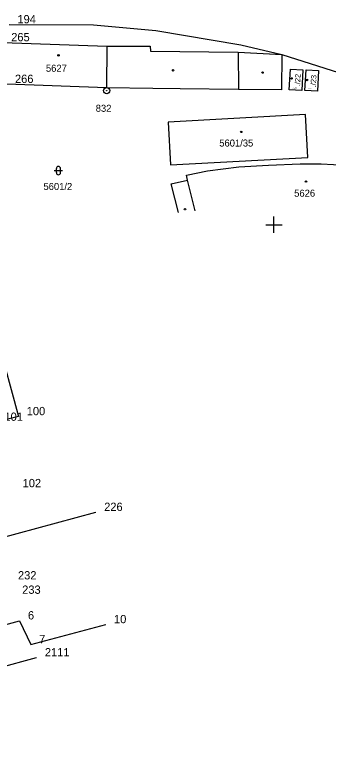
# Model space of a CAD drawing. Extents: x -822293 to -820259, y -1071573 to -1068794.
# Drawn here: x -821162.5 to -821086.9, y -1070329.7 to -1070149.3 of the extents above; entities that cross this region are included whole.
import ezdxf

# ---------------------------------------------------------------- set-up
doc = ezdxf.new("R2010")
doc.units = 0
for name, color, linetype in [('Vrstva 1', 7, 'Continuous'), ('Vrstva 16', 7, 'Continuous'), ('Vrstva 17', 7, 'Continuous'), ('Vrstva 18', 7, 'Continuous'), ('Vrstva 19', 7, 'Continuous'), ('Vrstva 2', 7, 'Continuous'), ('Vrstva 24', 7, 'Continuous'), ('Vrstva 25', 7, 'Continuous'), ('Vrstva 3', 7, 'Continuous'), ('Vrstva 62', 7, 'Continuous'), ('Vrstva 8', 7, 'Continuous'), ('Vrstva 9', 7, 'Continuous')]:
    doc.layers.add(name, color=color, linetype=linetype)

# ---------------------------------------------------------------- blocks, each defined once
blk = doc.blocks.new('02.04')
at = {"layer": 'Vrstva 1'}
for p, q in [((0, -2), (0, 2)), ((-2, 0), (2, 0))]:
    blk.add_line(p, q, dxfattribs=at)

msp = doc.modelspace()

# ---------------------------------------------------------------- linework, layer by layer
at = {"layer": 'Vrstva 1'}
for p, q in [((-821163.95, -1070151.61), (-821143.55, -1070151.69)), ((-821143.55, -1070151.69), (-821128.56, -1070153.06)), ((-821128.56, -1070153.06), (-821108, -1070156.52)), ((-821108, -1070156.52), (-821098.1, -1070158.83)), ((-821098.1, -1070158.83), (-821078.33, -1070165.11))]:
    msp.add_line(p, q, dxfattribs=at)
at = {"layer": 'Vrstva 2'}
for p, q in [((-821165.45, -1070155.95), (-821140.36, -1070156.81)), ((-821140.36, -1070156.81), (-821129.86, -1070156.83)), ((-821129.86, -1070156.83), (-821129.85, -1070158.03)), ((-821129.85, -1070158.03), (-821108.61, -1070158.27)), ((-821108.61, -1070158.27), (-821098.1, -1070158.83)), ((-821098.1, -1070158.83), (-821098.15, -1070167.39)), ((-821096.3, -1070167.37), (-821096.03, -1070162.37)), ((-821096.03, -1070162.37), (-821093, -1070162.53)), ((-821093, -1070162.53), (-821093.26, -1070167.53)), ((-821092.52, -1070167.57), (-821092.25, -1070162.57)), ((-821092.25, -1070162.57), (-821089.24, -1070162.74)), ((-821089.24, -1070162.74), (-821089.51, -1070167.73)), ((-821140.43, -1070166.93), (-821164.54, -1070166.03)), ((-821129.26, -1070167.05), (-821140.43, -1070166.93)), ((-821122.63, -1070167.12), (-821129.26, -1070167.05)), ((-821108.55, -1070167.27), (-821122.63, -1070167.12)), ((-821098.15, -1070167.39), (-821108.55, -1070167.27)), ((-821093.26, -1070167.53), (-821096.3, -1070167.37)), ((-821089.51, -1070167.73), (-821092.52, -1070167.57)), ((-821092.38, -1070173.39), (-821125.56, -1070175.19)), ((-821091.82, -1070183.72), (-821092.38, -1070173.39)), ((-821125.56, -1070175.19), (-821125, -1070185.51)), ((-821180.15, -1070178.8), (-821161.7, -1070246.35)), ((-821125, -1070185.51), (-821091.82, -1070183.72)), ((-821116.04, -1070186.99), (-821108.46, -1070186.03)), ((-821108.46, -1070186.03), (-821101.3, -1070185.59)), ((-821101.3, -1070185.59), (-821093.71, -1070185.3)), ((-821093.71, -1070185.3), (-821088.62, -1070185.31)), ((-821088.62, -1070185.31), (-821082.59, -1070185.59)), ((-821121.13, -1070188.01), (-821116.04, -1070186.99)), ((-821120.9, -1070189.23), (-821121.13, -1070188.01)), ((-821124.79, -1070190.12), (-821120.9, -1070189.23)), ((-821123.019, -1070197.032), (-821124.79, -1070190.12)), ((-821161.7, -1070246.35), (-821167.08, -1070247.71)), ((-821181.65, -1070279.98), (-821143, -1070269.5)), ((-821238.1, -1070316.46), (-821161.41, -1070295.73)), ((-821161.41, -1070295.73), (-821158.7, -1070301.47)), ((-821158.7, -1070301.47), (-821140.63, -1070296.64)), ((-821258.12, -1070332.09), (-821157.32, -1070304.65))]:
    msp.add_line(p, q, dxfattribs=at)
at = {"layer": 'Vrstva 24'}
for radius in [0.75, 0.0327]:
    msp.add_circle((-821140.38, -1070167.57), radius, dxfattribs=at)
at = {"layer": 'Vrstva 25'}
for p, q in [((-821152.54, -1070187.41), (-821152.54, -1070186.41)), ((-821151.54, -1070187.41), (-821151.54, -1070186.41)), ((-821153.04, -1070186.91), (-821151.04, -1070186.91))]:
    msp.add_line(p, q, dxfattribs=at)
for centre in [(-821152.03, -1070159.04), (-821124.35, -1070162.67), (-821102.75, -1070163.22), (-821095.75, -1070164.63), (-821092.01, -1070165.01), (-821107.91, -1070177.55), (-821092.27, -1070189.57), (-821121.48, -1070196.26)]:
    msp.add_circle(centre, 0.175, dxfattribs=at)
for centre, start, end in [((-821152.04, -1070186.41), 0, 180), ((-821152.04, -1070187.41), 180, 0)]:
    msp.add_arc(centre, 0.5, start, end, dxfattribs=at)
at = {"layer": 'Vrstva 3'}
for p, q in [((-821140.36, -1070156.81), (-821140.43, -1070166.93)), ((-821108.61, -1070158.27), (-821108.55, -1070167.27)), ((-821119.049, -1070196.614), (-821120.9, -1070189.23))]:
    msp.add_line(p, q, dxfattribs=at)
at = {"layer": 'Vrstva 8'}
for p, q in [((-821161.7, -1070246.35), (-821161.7, -1070246.35)), ((-821143, -1070269.5), (-821143, -1070269.5)), ((-821161.41, -1070295.73), (-821161.41, -1070295.73)), ((-821140.63, -1070296.64), (-821140.63, -1070296.64)), ((-821158.7, -1070301.47), (-821158.7, -1070301.47)), ((-821157.32, -1070304.65), (-821157.32, -1070304.65))]:
    msp.add_line(p, q, dxfattribs=at)

# ---------------------------------------------------------------- block references
at = {"layer": 'Vrstva 62'}
msp.add_blockref('02.04', (-821100, -1070200), dxfattribs=at)

# ---------------------------------------------------------------- texts
at = {"layer": 'Vrstva 16'}
for s, rotation, p in [('./22', 87.02595, (-821093.711, -1070166.558)), ('./23', 86.90472, (-821089.894, -1070166.815))]:
    msp.add_text(s, height=1.3, rotation=rotation, dxfattribs=at).set_placement(p)
at = {"layer": 'Vrstva 17'}
msp.add_text('832', height=1.7, dxfattribs=at).set_placement((-821143.042, -1070172.7))
at = {"layer": 'Vrstva 18'}
msp.add_text('5601/2', height=1.7, dxfattribs=at).set_placement((-821155.66, -1070191.6))
at = {"layer": 'Vrstva 19'}
for s, height, p in [('5627', 1.7, (-821155.064, -1070163.02)), ('5601/22', 0.2, (-821095.525, -1070166.99)), ('5601/23', 0.2, (-821091.696, -1070167.22)), ('5601/35', 1.7, (-821113.212, -1070181.1)), ('5626', 1.7, (-821095.119, -1070193.23))]:
    msp.add_text(s, height=height, dxfattribs=at).set_placement(p)
at = {"layer": 'Vrstva 9'}
for s, p in [('194', (-821161.95, -1070151.31)), ('265', (-821163.45, -1070155.65)), ('266', (-821162.54, -1070165.73)), ('100', (-821159.7, -1070246.05)), ('101', (-821165.08, -1070247.41)), ('102', (-821160.69, -1070263.46)), ('226', (-821141, -1070269.2)), ('232', (-821161.81, -1070285.75)), ('233', (-821160.8, -1070289.23)), ('6', (-821159.41, -1070295.43)), ('10', (-821138.63, -1070296.34)), ('7', (-821156.7, -1070301.17)), ('2111', (-821155.32, -1070304.35))]:
    msp.add_text(s, height=2, dxfattribs=at).set_placement(p)

doc.saveas('drawing.dxf')
